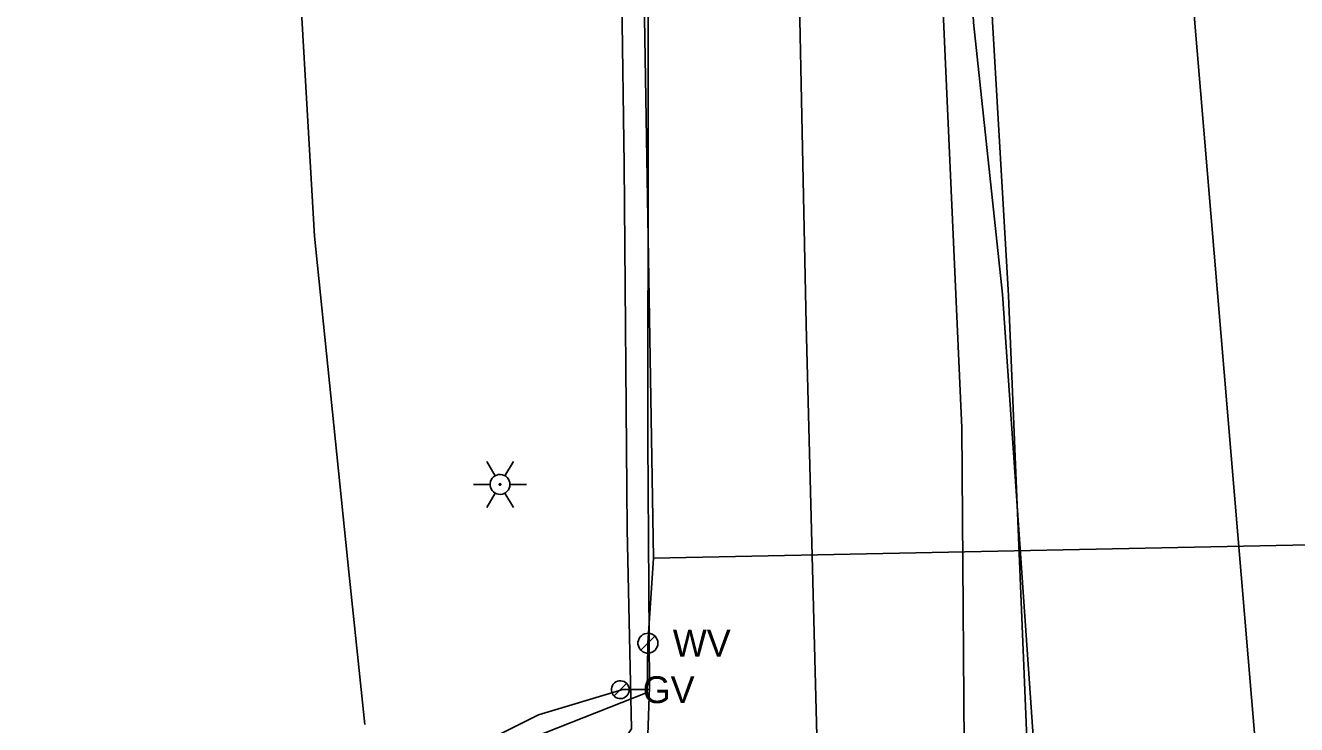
# Model space of a CAD drawing. Extents: x 596028 to 606371, y 330010 to 403088.
# Drawn here: x 604758.9 to 604941.1, y 333834.7 to 333935 of the extents above; entities that cross this region are included whole.
import ezdxf

# ---------------------------------------------------------------- set-up
doc = ezdxf.new("R2010")
doc.units = 0
for name, color, linetype in [('E_FTMS_Conduit', 7, 'Continuous'), ('E_LTG', 7, 'Continuous'), ('E_LTG_CID', 7, 'Continuous'), ('E_UTL_E_UG', 7, 'Continuous'), ('E_UTL_FO_UG_QWEST', 7, 'Continuous'), ('E_UTL_G', 7, 'Continuous'), ('E_UTL_G_UG', 7, 'Continuous'), ('E_UTL_SAN_UG_MMSD', 7, 'Continuous'), ('E_UTL_T_UG', 7, 'Continuous'), ('E_UTL_W', 7, 'Continuous'), ('E_UTL_W_UG', 7, 'Continuous')]:
    doc.layers.add(name, color=color, linetype=linetype)

msp = doc.modelspace()

# ---------------------------------------------------------------- linework, layer by layer
at = {"layer": 'E_FTMS_Conduit'}
msp.add_lwpolyline([(604896.64, 333466.11), (604897.17, 333555.99), (604901.76, 333584.15), (604905.09, 333639.3), (604905.9, 333684.1), (604904.77, 333712.67), (604904.93, 333775.72), (604905.22, 333800.4), (604903.67, 333828.24), (604898.91, 333896.44), (604894.79, 333935.39), (604893.25, 333968.09), (604888.86, 334043.3), (604889.85, 334080.96), (604885.17, 334157.03), (604884.79, 334195.8)], dxfattribs=at)
at = {"layer": 'E_LTG'}
for points in [[(604826.23, 333870.41), (604825.03, 333872.47)], [(604827.65, 333870.41), (604828.85, 333872.47)], [(604828.37, 333869.17), (604828.34, 333869.44), (604828.27, 333869.7), (604828.14, 333869.95), (604827.97, 333870.16), (604827.77, 333870.34), (604827.53, 333870.47), (604827.28, 333870.56), (604827.01, 333870.6), (604826.74, 333870.59), (604826.47, 333870.52), (604826.23, 333870.41), (604826, 333870.25), (604825.82, 333870.06), (604825.67, 333869.83), (604825.57, 333869.58), (604825.52, 333869.31), (604825.52, 333869.04), (604825.57, 333868.77), (604825.67, 333868.52), (604825.82, 333868.29), (604826, 333868.09), (604826.23, 333867.94), (604826.47, 333867.82), (604826.74, 333867.76), (604827.01, 333867.75), (604827.28, 333867.78), (604827.53, 333867.87), (604827.77, 333868.01), (604827.97, 333868.19), (604828.14, 333868.4), (604828.27, 333868.64), (604828.34, 333868.9), (604828.37, 333869.17)], [(604828.37, 333869.17), (604828.34, 333869.44), (604828.27, 333869.7), (604828.14, 333869.95), (604827.97, 333870.16), (604827.77, 333870.34), (604827.53, 333870.47), (604827.28, 333870.56), (604827.01, 333870.6), (604826.74, 333870.59), (604826.47, 333870.52), (604826.23, 333870.41), (604826, 333870.25), (604825.82, 333870.06), (604825.67, 333869.83), (604825.57, 333869.58), (604825.52, 333869.31), (604825.52, 333869.04), (604825.57, 333868.77), (604825.67, 333868.52), (604825.82, 333868.29), (604826, 333868.09), (604826.23, 333867.94), (604826.47, 333867.82), (604826.74, 333867.76), (604827.01, 333867.75), (604827.28, 333867.78), (604827.53, 333867.87), (604827.77, 333868.01), (604827.97, 333868.19), (604828.14, 333868.4), (604828.27, 333868.64), (604828.34, 333868.9), (604828.37, 333869.17)], [(604828.37, 333869.17), (604828.34, 333869.44), (604828.27, 333869.7), (604828.14, 333869.95), (604827.97, 333870.16), (604827.77, 333870.34), (604827.53, 333870.47), (604827.28, 333870.56), (604827.01, 333870.6), (604826.74, 333870.59), (604826.47, 333870.52), (604826.23, 333870.41), (604826, 333870.25), (604825.82, 333870.06), (604825.67, 333869.83), (604825.57, 333869.58), (604825.52, 333869.31), (604825.52, 333869.04), (604825.57, 333868.77), (604825.67, 333868.52), (604825.82, 333868.29), (604826, 333868.09), (604826.23, 333867.94), (604826.47, 333867.82), (604826.74, 333867.76), (604827.01, 333867.75), (604827.28, 333867.78), (604827.53, 333867.87), (604827.77, 333868.01), (604827.97, 333868.19), (604828.14, 333868.4), (604828.27, 333868.64), (604828.34, 333868.9), (604828.37, 333869.17)], [(604827.06, 333869.17), (604827.06, 333869.2), (604827.05, 333869.22), (604827.04, 333869.24), (604827.03, 333869.26), (604827.01, 333869.27), (604826.99, 333869.28), (604826.97, 333869.29), (604826.95, 333869.29), (604826.92, 333869.29), (604826.9, 333869.29), (604826.88, 333869.28), (604826.86, 333869.26), (604826.85, 333869.25), (604826.83, 333869.23), (604826.83, 333869.21), (604826.82, 333869.18), (604826.82, 333869.16), (604826.83, 333869.14), (604826.83, 333869.12), (604826.85, 333869.1), (604826.86, 333869.08), (604826.88, 333869.07), (604826.9, 333869.06), (604826.92, 333869.06), (604826.95, 333869.05), (604826.97, 333869.06), (604826.99, 333869.06), (604827.01, 333869.08), (604827.03, 333869.09), (604827.04, 333869.11), (604827.05, 333869.13), (604827.06, 333869.15), (604827.06, 333869.17)], [(604823.13, 333869.17), (604825.51, 333869.17)], [(604825.03, 333865.87), (604826.23, 333867.94)], [(604828.85, 333865.87), (604827.65, 333867.94)], [(604828.37, 333869.17), (604830.75, 333869.17)]]:
    msp.add_lwpolyline(points, dxfattribs=at)
at = {"layer": 'E_LTG_CID'}
msp.add_lwpolyline([(604898.66, 333648.41), (604897.89, 333658.49), (604903.28, 333683.61), (604906.21, 333712.23), (604905.7, 333775.82), (604903.51, 333800.38), (604902.62, 333828.09), (604899.81, 333896.26), (604897.48, 333935.5), (604896.01, 333968.2), (604892.28, 334044.57), (604891.28, 334080.98), (604886.48, 334157.87), (604883.68, 334195.04)], dxfattribs=at)
at = {"layer": 'E_UTL_E_UG'}
for points in [[(604877.02, 333463.99), (604875.73, 333577.42), (604874.92, 333635.7), (604875.14, 333666.02), (604873.55, 333754.91), (604872.54, 333805.97), (604872.79, 333814.74), (604870.78, 333892.12), (604869.22, 333968.06), (604869.63, 334026.67), (604868.32, 334082.91), (604866.08, 334139.89), (604863.78, 334185.83), (604861.75, 334225.99), (604854.45, 334356.74)], [(604807.59, 333834.76), (604805.26, 333856.62), (604800.37, 333904.78), (604797.43, 333955.12), (604794.17, 334006.19), (604805.24, 334046.05)]]:
    msp.add_lwpolyline(points, dxfattribs=at)
at = {"layer": 'E_UTL_FO_UG_QWEST'}
msp.add_lwpolyline([(604064.36, 333597.95), (604125.52, 333607.24), (604222.69, 333622.89), (604294.58, 333635.82), (604348.76, 333642.01), (604429.81, 333649.86), (604519.71, 333664), (604602.19, 333686.85), (604652.71, 333705.68), (604723.21, 333725.29), (604801.25, 333748.09), (604835.09, 333762.42), (604848.03, 333769.94), (604883.85, 333785.99), (604890.17, 333789.47), (604890.94, 333790.11), (604892.16, 333796.08), (604892.06, 333804.65), (604893.55, 333818.96), (604893.11, 333877.27), (604889.73, 333952.96), (604886.58, 334030.08), (604884.67, 334105.68), (604880.28, 334183.13)], dxfattribs=at)
at = {"layer": 'E_UTL_G'}
for points in [[(604845.46, 333839.75), (604845.44, 333839.99), (604845.37, 333840.22), (604845.26, 333840.44), (604845.1, 333840.63), (604844.92, 333840.79), (604844.71, 333840.91), (604844.48, 333840.99), (604844.24, 333841.03), (604843.99, 333841.02), (604843.76, 333840.96), (604843.53, 333840.86), (604843.34, 333840.72), (604843.17, 333840.54), (604843.04, 333840.33), (604842.94, 333840.11), (604842.9, 333839.87), (604842.9, 333839.62), (604842.94, 333839.38), (604843.04, 333839.16), (604843.17, 333838.95), (604843.34, 333838.78), (604843.53, 333838.63), (604843.76, 333838.53), (604843.99, 333838.48), (604844.24, 333838.46), (604844.48, 333838.5), (604844.71, 333838.58), (604844.92, 333838.7), (604845.1, 333838.86), (604845.26, 333839.05), (604845.37, 333839.27), (604845.44, 333839.5), (604845.46, 333839.75)], [(604843.27, 333838.84), (604845.08, 333840.65)]]:
    msp.add_lwpolyline(points, dxfattribs=at)
at = {"layer": 'E_UTL_G_UG'}
for points in [[(604847.97, 333829.11), (604848.35, 333840.17), (604848.14, 333875.54), (604848.22, 333961.6), (604847.47, 334017.45), (604847.16, 334022.52)], [(604716.26, 333795.51), (604746.45, 333804.07), (604803.5, 333825.03), (604821.12, 333830.43), (604832.44, 333836.15), (604844.53, 333839.78), (604848.34, 333839.76)]]:
    msp.add_lwpolyline(points, dxfattribs=at)
at = {"layer": 'E_UTL_SAN_UG_MMSD'}
msp.add_lwpolyline([(604978.83, 333311.92), (604918.55, 334029.79), (604889.58, 334663.41)], dxfattribs=at)
at = {"layer": 'E_UTL_T_UG'}
msp.add_lwpolyline([(604287.56, 333667.46), (604321.18, 333666.93), (604440.94, 333666.46), (604493.47, 333670.08), (604529.7, 333676.11), (604555.97, 333682.92), (604653.39, 333710.18), (604723.28, 333734.82), (604777.43, 333753.12), (604798.61, 333759.72), (604824.33, 333769.22), (604827.36, 333771.7), (604818.65, 333799.13), (604813.51, 333815.63), (604833.03, 333823.91), (604843.16, 333830.13), (604845.76, 333834.11), (604845.18, 333862.78), (604844.73, 333915.07), (604844.08, 333962.32)], dxfattribs=at)
at = {"layer": 'E_UTL_W'}
for points in [[(604849.56, 333846.41), (604849.53, 333846.68), (604849.45, 333846.94), (604849.33, 333847.18), (604849.16, 333847.4), (604848.96, 333847.58), (604848.72, 333847.71), (604848.47, 333847.8), (604848.2, 333847.84), (604847.93, 333847.82), (604847.66, 333847.76), (604847.42, 333847.65), (604847.2, 333847.49), (604847.01, 333847.3), (604846.86, 333847.07), (604846.76, 333846.82), (604846.71, 333846.55), (604846.71, 333846.28), (604846.76, 333846.01), (604846.86, 333845.76), (604847.01, 333845.53), (604847.2, 333845.34), (604847.42, 333845.18), (604847.66, 333845.07), (604847.93, 333845), (604848.2, 333844.99), (604848.47, 333845.03), (604848.72, 333845.12), (604848.96, 333845.25), (604849.16, 333845.43), (604849.33, 333845.64), (604849.45, 333845.88), (604849.53, 333846.14), (604849.56, 333846.41)], [(604847.12, 333845.41), (604849.14, 333847.42)]]:
    msp.add_lwpolyline(points, dxfattribs=at)
at = {"layer": 'E_UTL_W_UG'}
msp.add_line((604848.93, 333858.58), (605063.62, 333862.97), dxfattribs=at)
for points in [[(604848.13, 333846.41), (604848.93, 333858.58), (604847.5, 333944.73), (604845.77, 334042.88), (604845.13, 334077.17), (604844.27, 334161.95), (604839.18, 334215.87), (604837.01, 334265.02), (604832.72, 334352.02), (604829.86, 334407.8), (604827.89, 334453.7), (604825.43, 334498.81), (604823.81, 334547.5), (604822.62, 334574.16), (604815.88, 334728.21), (604813.65, 334769.04), (604806.31, 334937.47), (604805.78, 334961.33), (604795.52, 335171.8)], [(604515.23, 333705.55), (604537.69, 333723.74), (604678.54, 333766.26), (604808.21, 333809.92), (604813.3, 333825.61), (604848.02, 333839.34), (604848.13, 333846.41)]]:
    msp.add_lwpolyline(points, dxfattribs=at)

# ---------------------------------------------------------------- texts
at = {"layer": 'E_UTL_G'}
msp.add_text('GV', height=3.85, dxfattribs=at).set_placement((604847.38, 333837.82))
at = {"layer": 'E_UTL_W'}
msp.add_text('WV', height=3.85, dxfattribs=at).set_placement((604851.7, 333844.49))

doc.saveas('drawing.dxf')
